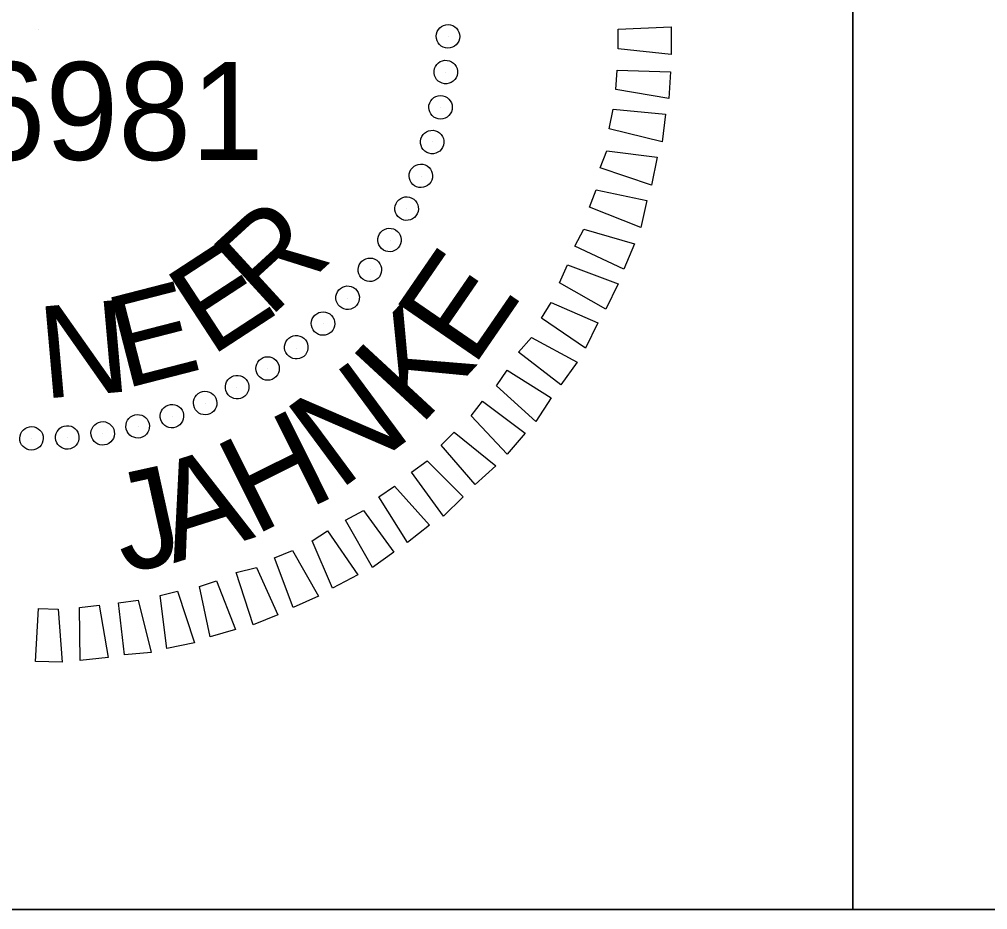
# Model space of a CAD drawing. Extents: x 3025871 to 3026431, y 707165 to 707825.
# Drawn here: x 3026249.41 to 3026258.31, y 707363 to 707371.19 of the extents above; entities that cross this region are included whole.
import ezdxf

# ---------------------------------------------------------------- set-up
doc = ezdxf.new("R2010")
doc.units = 0
for name, color, linetype in [('Old_Level_19', 7, 'Continuous'), ('Sheet Block Title CELL', 7, 'Continuous'), ('Sheet Cutting Line CELL', 7, 'Continuous')]:
    doc.layers.add(name, color=color, linetype=linetype)

msp = doc.modelspace()

# ---------------------------------------------------------------- linework, layer by layer
at = {"layer": 'Old_Level_19'}
msp.add_line((3026242.0652, 707363.0021), (3026272.0708, 707363.0021), dxfattribs=at)
at = {"layer": 'Sheet Block Title CELL'}
for p, q in [((3026249.5907, 707371.0966), (3026249.5907, 707371.0966)), ((3026253.3557, 707371.0291), (3026253.3557, 707371.0291)), ((3026253.3332, 707370.6991), (3026253.3332, 707370.6991)), ((3026253.2807, 707370.3766), (3026253.2807, 707370.3766)), ((3026253.2132, 707370.0616), (3026253.2132, 707370.0616)), ((3026253.1082, 707369.7466), (3026253.1082, 707369.7466)), ((3026252.9732, 707369.4466), (3026252.9732, 707369.4466)), ((3026252.8232, 707369.1541), (3026252.8232, 707369.1541)), ((3026252.6357, 707368.8841), (3026252.6357, 707368.8841)), ((3026252.4332, 707368.6216), (3026252.4332, 707368.6216)), ((3026252.2082, 707368.3891), (3026252.2082, 707368.3891)), ((3026251.9607, 707368.1641), (3026251.9607, 707368.1641)), ((3026251.6982, 707367.9766), (3026251.6982, 707367.9766)), ((3026251.4132, 707367.8041), (3026251.4132, 707367.8041)), ((3026251.1207, 707367.6541), (3026251.1207, 707367.6541)), ((3026250.8207, 707367.5341), (3026250.8207, 707367.5341)), ((3026250.5057, 707367.4441), (3026250.5057, 707367.4441)), ((3026250.1757, 707367.3841), (3026250.1757, 707367.3841)), ((3026249.5232, 707367.3316), (3026249.5232, 707367.3316)), ((3026249.8532, 707367.3391), (3026249.8532, 707367.3391))]:
    msp.add_line(p, q, dxfattribs=at)
for points in [[(3026254.9157, 707371.0966), (3026255.4032, 707371.1191), (3026255.4032, 707370.8641), (3026254.9157, 707370.9166)], [(3026254.9082, 707370.7216), (3026255.3957, 707370.7066), (3026255.3807, 707370.4591), (3026254.8932, 707370.5416)], [(3026254.8707, 707370.3616), (3026255.3507, 707370.3166), (3026255.3207, 707370.0616), (3026254.8332, 707370.1816)], [(3026254.8107, 707369.9791), (3026255.2757, 707369.9191), (3026255.2232, 707369.6641), (3026254.7507, 707369.8216)], [(3026254.7132, 707369.6191), (3026255.1782, 707369.5216), (3026255.1257, 707369.2741), (3026254.6532, 707369.4616)], [(3026254.6007, 707369.2591), (3026255.0657, 707369.1241), (3026254.9682, 707368.8916), (3026254.5182, 707369.1016)], [(3026254.4507, 707368.9291), (3026254.9157, 707368.7566), (3026254.8032, 707368.5241), (3026254.3757, 707368.7641)], [(3026254.3007, 707368.5841), (3026254.7282, 707368.3966), (3026254.6157, 707368.1641), (3026254.2107, 707368.4416)], [(3026254.1207, 707368.2616), (3026254.5407, 707368.0366), (3026254.3907, 707367.8266), (3026254.0007, 707368.1266)], [(3026253.8957, 707367.9616), (3026254.3007, 707367.7066), (3026254.1582, 707367.4891), (3026253.7982, 707367.8191)], [(3026253.6707, 707367.6766), (3026254.0607, 707367.3841), (3026253.8957, 707367.1891), (3026253.5657, 707367.5416)], [(3026253.4082, 707367.3916), (3026253.7907, 707367.0841), (3026253.6032, 707366.9116), (3026253.2882, 707367.2716)], [(3026253.1607, 707367.1291), (3026253.4907, 707366.7991), (3026253.3107, 707366.6191), (3026253.0182, 707367.0241)], [(3026252.8607, 707366.8966), (3026253.1832, 707366.5366), (3026252.9807, 707366.3791), (3026252.7182, 707366.7991)], [(3026252.5757, 707366.6716), (3026252.8532, 707366.2891), (3026252.6582, 707366.1466), (3026252.4107, 707366.5816)], [(3026252.2457, 707366.4841), (3026252.5232, 707366.0791), (3026252.2907, 707365.9591), (3026252.1032, 707366.3941)], [(3026251.9232, 707366.3041), (3026252.1632, 707365.8841), (3026251.9307, 707365.7791), (3026251.7582, 707366.2366)], [(3026251.5932, 707366.1466), (3026251.7882, 707365.7116), (3026251.5632, 707365.6216), (3026251.4057, 707366.1016)], [(3026251.2257, 707366.0266), (3026251.3982, 707365.5766), (3026251.1657, 707365.5091), (3026251.0682, 707365.9741)], [(3026250.8657, 707365.9291), (3026251.0232, 707365.4566), (3026250.7682, 707365.4041), (3026250.7082, 707365.8916)], [(3026250.5057, 707365.8466), (3026250.6257, 707365.3666), (3026250.3782, 707365.3441), (3026250.3257, 707365.8241)], [(3026249.7707, 707365.7641), (3026249.8082, 707365.2766), (3026249.5607, 707365.2841), (3026249.5907, 707365.7716)], [(3026250.1457, 707365.8016), (3026250.2282, 707365.3216), (3026249.9732, 707365.2916), (3026249.9657, 707365.7791)]]:
    msp.add_lwpolyline(points, close=True, dxfattribs=at)
for centre, major_axis in [((3026253.3522, 707371.0309), (0.108, -0.0019)), ((3026253.3321, 707370.7034), (0.1074, -0.0113)), ((3026253.2836, 707370.3788), (0.106, -0.0206)), ((3026253.207, 707370.0596), (0.1038, -0.0298)), ((3026253.1029, 707369.7484), (0.1008, -0.0387)), ((3026252.972, 707369.4474), (0.0971, -0.0473)), ((3026252.8154, 707369.159), (0.0926, -0.0556)), ((3026252.6343, 707368.8853), (0.0874, -0.0635)), ((3026252.43, 707368.6285), (0.0815, -0.0709)), ((3026252.204, 707368.3904), (0.075, -0.0777)), ((3026251.9582, 707368.173), (0.068, -0.0839)), ((3026251.6944, 707367.9777), (0.0604, -0.0895)), ((3026251.4146, 707367.8063), (0.0524, -0.0945)), ((3026251.1209, 707367.6598), (0.0439, -0.0987)), ((3026250.8155, 707367.5395), (0.0352, -0.1021)), ((3026250.5008, 707367.4463), (0.0261, -0.1048)), ((3026249.5251, 707367.3352), (-0.0019, -0.108)), ((3026249.8532, 707367.3438), (0.0075, -0.1077)), ((3026250.1792, 707367.3809), (0.0169, -0.1067))]:
    msp.add_ellipse(centre, major_axis=major_axis, ratio=0.999708, dxfattribs=at)
at = {"layer": 'Sheet Cutting Line CELL'}
msp.add_line((3026257.0727, 707379.8771), (3026257.0727, 707363.0096), dxfattribs=at)
for points in [[(3026242.0652, 707379.8771), (3026257.0727, 707379.8771), (3026257.0727, 707363.0021), (3026242.0652, 707363.0021)], [(3026257.0727, 707379.8771), (3026272.0727, 707379.8771), (3026272.0727, 707363.0021), (3026257.0727, 707363.0021)]]:
    msp.add_lwpolyline(points, close=True, dxfattribs=at)

# ---------------------------------------------------------------- texts
at = {"layer": 'Sheet Block Title CELL'}
msp.add_text('046981', height=0.89973, dxfattribs=at).set_placement((3026247.6451, 707369.8953))
for s, height, rotation, p in [('R', 0.8458, 42.48141, (3026251.7057, 707368.4341)), ('E', 0.8458, 33.12409, (3026251.1732, 707368.0816)), ('E', 0.8997, 55.49302, (3026253.5811, 707367.9778)), ('E', 0.8457, 14.41176, (3026250.3782, 707367.7891)), ('N', 0.8457, 5.05639, (3026249.6357, 707367.6991)), ('K', 0.8997, 47.2091, (3026253.0901, 707367.4354)), ('N', 0.8997, 36.48327, (3026252.3476, 707366.8481)), ('H', 0.8997, 26.49929, (3026251.5692, 707366.4345)), ('A', 0.8997, 17.65898, (3026250.8293, 707366.1858)), ('J', 0.8997, 12.40116, (3026250.374, 707366.093))]:
    msp.add_text(s, height=height, rotation=rotation, dxfattribs=at).set_placement(p)

doc.saveas('drawing.dxf')
